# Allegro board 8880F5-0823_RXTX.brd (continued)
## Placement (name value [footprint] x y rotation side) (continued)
NOREF#889  -  []  226.83 269.63 90 top
NOREF#890  -  []  209.33 242.68 90 top
NOREF#891  -  []  412.24 144.98 90 top
NOREF#892  -  []  201.23 201.89 90 top
NOREF#893  -  []  247.25 205.56 0 top
NOREF#894  -  []  412.6 161.74 0 top
NOREF#895  -  []  405.17 131.89 0 top
NOREF#896  -  []  392.47 272.66 90 top
NOREF#897  -  []  343.98 288.86 0 top
NOREF#898  -  []  321.82 167.13 90 top
NOREF#899  -  []  175.8 201.79 90 top
NOREF#900  -  []  184.47 165.4 90 top
NOREF#901  -  []  168.13 240.88 90 top
NOREF#902  -  []  265.81 288.86 0 top
NOREF#903  -  []  66.26 271.33 90 top
NOREF#904  -  []  309.51 253.69 0 top
NOREF#905  -  []  331.94 204.65 90 top
NOREF#906  -  []  352.25 244.23 0 top
NOREF#907  -  []  310.73 187.93 0 top
NOREF#908  -  []  407.77 255.47 0 top
NOREF#909  -  []  424.47 163.09 90 top
NOREF#910  -  []  313.94 286.96 90 top
NOREF#911  -  []  192.47 230.17 90 top
NOREF#912  -  []  184.47 227.72 90 top
NOREF#913  -  []  383.73 202.38 90 top
NOREF#914  -  []  331.22 193.63 0 top
NOREF#915  -  []  352.25 241.69 0 top
NOREF#916  -  []  167.7 231.27 90 top
NOREF#917  -  []  310.41 193.37 90 top
NOREF#918  -  []  192.47 150.58 90 top
NOREF#919  -  []  119.95 187.53 0 top
NOREF#920  -  []  383.09 241.11 0 top
NOREF#921  -  []  331.38 223.52 90 top
NOREF#922  -  []  93.76 287.84 90 top
NOREF#923  -  []  259.65 265.86 90 top
NOREF#924  -  []  119.76 127 90 top
NOREF#925  -  []  284.77 146.93 90 top
NOREF#926  -  []  332.51 265.56 0 top
NOREF#927  -  []  403.41 209.61 0 top
NOREF#928  -  []  461.86 182.17 90 top
NOREF#929  -  []  167.7 186.57 90 top
NOREF#930  -  []  396.55 273.11 0 top
NOREF#931  -  []  282.9 147.38 0 top
NOREF#932  -  []  333.4 205.55 0 top
NOREF#933  -  []  254.29 264.35 90 top
NOREF#934  -  []  251.94 204.65 90 top
NOREF#935  -  []  271.34 181.37 0 top
NOREF#936  -  []  319.33 183.63 90 top
NOREF#937  -  []  300.01 288.31 90 top
NOREF#938  -  []  367.48 225.87 90 top
NOREF#939  -  []  250.74 224.72 0 top
NOREF#940  -  []  371.73 281.11 0 top
NOREF#941  -  []  405.51 209.61 0 top
NOREF#942  -  []  166.06 230.19 90 top
NOREF#943  -  []  201.23 229.07 90 top
NOREF#944  -  []  305.94 296.86 0 top
NOREF#945  -  []  209.49 168.6 90 top
NOREF#946  -  []  392.04 224.85 90 top
NOREF#947  -  []  402.14 146.88 0 top
NOREF#948  -  []  330.17 165.04 90 top
NOREF#949  -  []  272.24 244.86 90 top
NOREF#950  -  []  384.17 180.15 90 top
NOREF#951  -  []  327.25 204.35 90 top
NOREF#952  -  []  309.21 188.88 0 top
NOREF#953  -  []  388.43 163.64 0 top
NOREF#954  -  []  405.93 240.56 90 top
NOREF#955  -  []  194.09 146.68 90 top
NOREF#956  -  []  332.51 205.56 90 top
NOREF#957  -  []  239.33 183.63 90 top
NOREF#958  -  []  228.36 262.16 45 top
NOREF#959  -  []  448.94 276.41 90 top
NOREF#960  -  []  112.41 214.71 0 top
NOREF#961  -  []  310.43 187.61 90 top
NOREF#962  -  []  334.61 265.86 90 top
NOREF#963  -  []  473.6 206.05 90 top
NOREF#964  -  []  209.33 201.79 90 top
NOREF#965  -  []  293.31 272.1 0 top
NOREF#966  -  []  165.8 144.78 0 top
NOREF#967  -  []  352.55 241.37 0 top
NOREF#968  -  []  352.25 185.5 0 top
NOREF#969  -  []  343.63 225.04 90 top
NOREF#970  -  []  352.24 244.86 90 top
NOREF#971  -  []  367.48 258.38 90 top
NOREF#972  -  []  175.7 202.99 90 top
NOREF#973  -  []  254.29 204.35 90 top
NOREF#974  -  []  330.51 288.86 0 top
NOREF#975  -  []  343.31 164.72 0 top
NOREF#976  -  []  253.4 204.35 90 top
NOREF#977  -  []  225.83 204.31 0 top
NOREF#978  -  []  201.49 163.2 90 top
NOREF#979  -  []  209.49 175.56 90 top
NOREF#980  -  []  262.04 224.74 0 top
NOREF#981  -  []  272.24 181.05 90 top
NOREF#982  -  []  201.23 247.18 90 top
NOREF#983  -  []  390.34 192.28 0 top
NOREF#984  -  []  258.35 288.91 90 top
NOREF#985  -  []  106.36 190.55 0 top
NOREF#986  -  []  346.27 132.97 90 top
NOREF#987  -  []  371.48 224.6 0 top
NOREF#988  -  []  230.73 193.69 0 top
NOREF#989  -  []  107.76 238.84 0 top
NOREF#990  -  []  475.04 239.09 0 top
NOREF#991  -  []  275.82 296.86 0 top
NOREF#992  -  []  110.21 195.15 0 top
NOREF#993  -  []  463.61 214.96 0 top
NOREF#994  -  []  398.53 161.74 90 top
NOREF#995  -  []  339.33 205.56 90 top
NOREF#996  -  []  229.21 246.34 0 top
NOREF#997  -  []  188.08 289.11 90 top
NOREF#998  -  []  389.7 209.36 0 top
NOREF#999  -  []  392.47 224.4 90 top
NOREF#1000  -  []  343.95 224.74 90 top
NOREF#1001  -  []  351.34 181.37 0 top
NOREF#1002  -  []  330.73 265.55 0 top
NOREF#1003  -  []  468.01 171.53 0 top
NOREF#1004  -  []  223.56 233.86 90 top
NOREF#1005  -  []  261.63 195.43 90 top
NOREF#1006  -  []  478.57 293.82 90 top
NOREF#1007  -  []  209.08 256.4 90 top
NOREF#1008  -  []  394.05 223.21 0 top
NOREF#1009  -  []  424.98 146.33 90 top
NOREF#1010  -  []  36.1 129.71 90 top
NOREF#1011  -  []  192.47 243.88 90 top
NOREF#1012  -  []  283.21 270.2 90 top
NOREF#1013  -  []  119.7 231.22 0 top
NOREF#1014  -  []  199.59 216.47 90 top
NOREF#1015  -  []  192.47 216.45 90 top
NOREF#1016  -  []  389.7 209.36 0 top
NOREF#1017  -  []  257.09 224.74 90 top
NOREF#1018  -  []  254.29 265.56 90 top
NOREF#1019  -  []  327.15 286.96 90 top
NOREF#1020  -  []  218.16 237.06 0 top
NOREF#1021  -  []  251.62 205.56 90 top
NOREF#1022  -  []  461.96 210.36 0 top
NOREF#1023  -  []  340.61 286.96 90 top
NOREF#1024  -  []  299.59 288.86 90 top
NOREF#1025  -  []  289.29 296.86 0 top
NOREF#1026  -  []  175.7 164.3 90 top
NOREF#1027  -  []  238.3 224.74 90 top
NOREF#1028  -  []  218.16 188.49 0 top
NOREF#1029  -  []  392.73 154.88 0 top
NOREF#1030  -  []  327.57 264.65 90 top
NOREF#1031  -  []  167.7 233.47 90 top
NOREF#1032  -  []  310.43 188.88 90 top
NOREF#1033  -  []  250.5 288.86 0 top
NOREF#1034  -  []  247.57 204.65 90 top
NOREF#1035  -  []  352.55 245.18 0 top
NOREF#1036  -  []  184.47 255.15 0 top
NOREF#1037  -  []  344.37 128.27 0 top
NOREF#1038  -  []  167.7 165.4 90 top
NOREF#1039  -  []  371.48 265.11 0 top
NOREF#1040  -  []  352.24 243.59 90 top
NOREF#1041  -  []  337.09 224.74 90 top
NOREF#1042  -  []  393.74 131.34 90 top
NOREF#1043  -  []  215.96 237.06 0 top
NOREF#1044  -  []  194.09 201.29 90 top
NOREF#1045  -  []  271.04 189.18 0 top
NOREF#1046  -  []  263.14 270.2 90 top
NOREF#1047  -  []  495.08 277.31 90 top
NOREF#1048  -  []  391.8 209.36 0 top
NOREF#1049  -  []  306.83 269.63 90 top
NOREF#1050  -  []  528.1 257.36 90 top
NOREF#1051  -  []  127.55 184.33 90 top
NOREF#1052  -  []  371.73 273.11 0 top
NOREF#1053  -  []  481.96 273.87 90 top
NOREF#1054  -  []  418.12 273.37 0 top
NOREF#1055  -  []  167.7 163.2 90 top
NOREF#1056  -  []  277.17 288.86 0 top
NOREF#1057  -  []  460.93 182.17 90 top
NOREF#1058  -  []  226.85 271.67 0 top
NOREF#1059  -  []  394.66 226.38 90 top
NOREF#1060  -  []  518.38 259.9 90 top
NOREF#1061  -  []  378.33 257.11 90 top
NOREF#1062  -  []  415.61 185.72 90 top
NOREF#1063  -  []  295.96 248.49 0 top
NOREF#1064  -  []  342.08 290.13 90 top
NOREF#1065  -  []  209.59 174.36 90 top
NOREF#1066  -  []  167.7 165.4 90 top
NOREF#1067  -  []  224.65 271.67 0 top
NOREF#1068  -  []  374.88 217.11 0 top
NOREF#1069  -  []  303.84 288.86 0 top
NOREF#1070  -  []  230.41 186.34 90 top
NOREF#1071  -  []  167.7 255.15 90 top
NOREF#1072  -  []  108.27 171.02 0 top
NOREF#1073  -  []  451.68 230.2 0 top
NOREF#1074  -  []  373.73 207.21 0 top
NOREF#1075  -  []  272.25 184.86 90 top
NOREF#1076  -  []  184.47 187.92 90 top
NOREF#1077  -  []  369.63 289.12 0 top
NOREF#1078  -  []  251.94 205.86 90 top
NOREF#1079  -  []  267.84 280.1 0 top
NOREF#1080  -  []  373.93 297.12 0 top
NOREF#1081  -  []  415.6 146.88 0 top
NOREF#1082  -  []  331.94 265.86 90 top
NOREF#1083  -  []  369.38 257.11 0 top
NOREF#1084  -  []  249.6 224.74 90 top
NOREF#1085  -  []  236.27 289.16 90 top
NOREF#1086  -  []  369.38 224.6 0 top
NOREF#1087  -  []  329.85 224.74 0 top
NOREF#1088  -  []  253.4 205.56 0 top
NOREF#1089  -  []  165.8 212.85 90 top
NOREF#1090  -  []  238.3 223.52 90 top
NOREF#1091  -  []  377.48 273.16 90 top
NOREF#1092  -  []  380.59 287.22 0 top
NOREF#1093  -  []  375.22 180.15 0 top
NOREF#1094  -  []  468.85 257.36 90 top
NOREF#1095  -  []  271.31 288.86 0 top
NOREF#1096  -  []  330.74 164.72 0 top
NOREF#1097  -  []  351.34 182.64 0 top
NOREF#1098  -  []  331.06 223.82 90 top
NOREF#1099  -  []  268.01 296.86 0 top
NOREF#1100  -  []  182.57 185.42 0 top
NOREF#1101  -  []  322.62 139.64 0 top
NOREF#1102  -  []  396.22 139.89 0 top
NOREF#1103  -  []  229.51 253.69 0 top
NOREF#1104  -  []  216.96 180.71 0 top
NOREF#1105  -  []  241.82 227.13 90 top
NOREF#1106  -  []  343.95 164.74 90 top
NOREF#1107  -  []  352.25 245.5 0 top
NOREF#1108  -  []  352.25 184.23 0 top
NOREF#1109  -  []  415.61 181.32 90 top
NOREF#1110  -  []  303.56 233.86 90 top
NOREF#1111  -  []  352.25 189.82 0 top
NOREF#1112  -  []  251.33 140.14 0 top
NOREF#1113  -  []  352.24 184.86 90 top
NOREF#1114  -  []  334.29 205.55 0 top
NOREF#1115  -  []  400.85 281.11 0 top
NOREF#1116  -  []  465.81 171.53 0 top
NOREF#1117  -  []  330.74 224.72 0 top
NOREF#1118  -  []  252.83 265.86 90 top
NOREF#1119  -  []  310.73 193.69 0 top
NOREF#1120  -  []  304.61 131.64 0 top
NOREF#1121  -  []  184.47 217.55 90 top
NOREF#1122  -  []  251.62 205.56 0 top
NOREF#1123  -  []  167.7 136.27 90 top
NOREF#1124  -  []  192.57 215.25 90 top
NOREF#1125  -  []  303.26 139.64 0 top
NOREF#1126  -  []  270.04 280.1 0 top
NOREF#1127  -  []  221.56 239.06 0 top
NOREF#1128  -  []  379 288.57 90 top
NOREF#1129  -  []  383.01 139.89 0 top
NOREF#1130  -  []  184.47 174.46 90 top
NOREF#1131  -  []  200.98 258.7 90 top
NOREF#1132  -  []  397.38 180.15 90 top
NOREF#1133  -  []  249.28 225.04 90 top
NOREF#1134  -  []  216.96 192.14 0 top
NOREF#1135  -  []  184.47 256.5 90 top
NOREF#1136  -  []  388.43 180.15 0 top
NOREF#1137  -  []  424.05 163.64 90 top
NOREF#1138  -  []  229.51 189.2 0 top
NOREF#1139  -  []  342.36 163.82 90 top
NOREF#1140  -  []  199.84 162.12 90 top
NOREF#1141  -  []  263.31 164.74 0 top
NOREF#1142  -  []  209.49 148.63 90 top
NOREF#1143  -  []  342.36 165.04 90 top
NOREF#1144  -  []  352.25 242.96 0 top
NOREF#1145  -  []  453.88 214.96 0 top
NOREF#1146  -  []  262.68 223.52 90 top
NOREF#1147  -  []  107.02 171.57 0 top
NOREF#1148  -  []  112.67 171.02 0 top
NOREF#1149  -  []  312.21 144.34 0 top
NOREF#1150  -  []  219.81 213.69 90 top
NOREF#1151  -  []  250.17 163.82 90 top
NOREF#1152  -  []  379.52 188.15 0 top
NOREF#1153  -  []  398.65 289.12 0 top
NOREF#1154  -  []  377.32 163.39 0 top
NOREF#1155  -  []  318.3 223.52 90 top
NOREF#1156  -  []  390.59 195.9 90 top
NOREF#1157  -  []  398.65 297.12 0 top
NOREF#1158  -  []  378.33 241.11 90 top
NOREF#1159  -  []  120.24 171.1 0 top
NOREF#1160  -  []  250.73 264.35 90 top
NOREF#1161  -  []  404.4 241.16 90 top
NOREF#1162  -  []  199.33 240.28 0 top
NOREF#1163  -  []  286.12 288.86 90 top
NOREF#1164  -  []  209.23 189.02 90 top
NOREF#1165  -  []  257.09 163.52 90 top
NOREF#1166  -  []  118.7 188.08 0 top
NOREF#1167  -  []  378.58 273.11 90 top
NOREF#1168  -  []  250.18 182.88 0 top
NOREF#1169  -  []  246.63 142.04 0 top
NOREF#1170  -  []  192.47 148.38 90 top
NOREF#1171  -  []  251.62 205.55 0 top
NOREF#1172  -  []  310.41 253.37 90 top
NOREF#1173  -  []  167.7 192.32 90 top
NOREF#1174  -  []  272.25 182.32 90 top
NOREF#1175  -  []  165.8 240.28 90 top
NOREF#1176  -  []  400.85 249.11 0 top
NOREF#1177  -  []  223.15 211.32 90 top
NOREF#1178  -  []  254.61 205.86 90 top
NOREF#1179  -  []  263.31 224.72 0 top
NOREF#1180  -  []  166.06 135.19 90 top
NOREF#1181  -  []  385.93 178.25 0 top
NOREF#1182  -  []  385.19 281.11 0 top
NOREF#1183  -  []  201.21 290.01 90 top
NOREF#1184  -  []  201.23 214 90 top
NOREF#1185  -  []  416.03 179.42 90 top
NOREF#1186  -  []  352.55 182.64 0 top
NOREF#1187  -  []  330.17 223.82 90 top
NOREF#1188  -  []  342.04 164.72 0 top
NOREF#1189  -  []  309.05 271.67 0 top
NOREF#1190  -  []  216.96 252.14 0 top
NOREF#1191  -  []  411.99 178.25 90 top
NOREF#1192  -  []  107.76 238.84 0 top
NOREF#1193  -  []  295.96 177.06 0 top
NOREF#1194  -  []  448.94 290.38 90 top
NOREF#1195  -  []  451.68 195.91 0 top
NOREF#1196  -  []  230.43 193.37 90 top
NOREF#1197  -  []  302.71 132.91 90 top
NOREF#1198  -  []  201.23 204.09 90 top
NOREF#1199  -  []  230.43 188.88 90 top
NOREF#1200  -  []  119.95 187.53 0 top
NOREF#1201  -  []  221.56 250.49 0 top
NOREF#1202  -  []  194.09 228.47 90 top
NOREF#1203  -  []  241.6 296.61 0 top
NOREF#1204  -  []  310.83 164.63 0 top
NOREF#1205  -  []  385.32 178.25 90 top
NOREF#1206  -  []  124.35 195.15 0 top
NOREF#1207  -  []  124.1 231.22 0 top
NOREF#1208  -  []  317.66 164.74 0 top
NOREF#1209  -  []  175.7 168.6 90 top
NOREF#1210  -  []  342.04 224.74 0 top
NOREF#1211  -  []  263.85 273.37 90 top
NOREF#1212  -  []  399.07 208.81 90 top
NOREF#1213  -  []  201.49 159.65 0 top
NOREF#1214  -  []  396.55 241.11 0 top
NOREF#1215  -  []  461.86 187.32 0 top
NOREF#1216  -  []  249.28 165.04 90 top
NOREF#1217  -  []  412.37 257.37 0 top
NOREF#1218  -  []  230.43 253.37 0 top
NOREF#1219  -  []  199.59 230.19 90 top
NOREF#1220  -  []  184.47 159.65 90 top
NOREF#1221  -  []  262.04 224.72 0 top
NOREF#1222  -  []  272.25 242.96 0 top
NOREF#1223  -  []  410.52 273.37 0 top
NOREF#1224  -  []  459.28 236.14 90 top
NOREF#1225  -  []  334.61 264.65 90 top
NOREF#1226  -  []  395.2 265.37 0 top
NOREF#1227  -  []  327.57 265.86 90 top
NOREF#1228  -  []  250.49 224.74 90 top
NOREF#1229  -  []  269.94 135.19 0 top
NOREF#1230  -  []  167.7 206.29 90 top
NOREF#1231  -  []  165.8 226.57 90 top
NOREF#1232  -  []  392.66 192.88 90 top
NOREF#1233  -  []  253.72 264.65 90 top
NOREF#1234  -  []  230.73 253.69 0 top
NOREF#1235  -  []  271.04 185.5 0 top
NOREF#1236  -  []  453.84 222.5 0 top
NOREF#1237  -  []  254.29 265.56 0 top
NOREF#1238  -  []  369.63 289.12 0 top
NOREF#1239  -  []  253.33 181.33 90 top
NOREF#1240  -  []  277.5 155.38 0 top
NOREF#1241  -  []  352.25 182.32 90 top
NOREF#1242  -  []  108.01 195.15 0 top
NOREF#1243  -  []  305.83 264.31 0 top
NOREF#1244  -  []  408.63 290.39 90 top
NOREF#1245  -  []  317.66 224.74 0 top
NOREF#1246  -  []  175.7 154.88 90 top
NOREF#1247  -  []  392.24 199.18 90 top
NOREF#1248  -  []  326 288.86 90 top
NOREF#1249  -  []  230.73 243.41 0 top
NOREF#1250  -  []  311.69 288.91 90 top
NOREF#1251  -  []  118.99 166.5 90 top
NOREF#1252  -  []  352.24 181.05 90 top
NOREF#1253  -  []  406.95 131.44 90 top
NOREF#1254  -  []  177.33 187.32 90 top
NOREF#1255  -  []  374.08 195.9 90 top
NOREF#1256  -  []  465.81 222.58 0 top
NOREF#1257  -  []  116.01 222.33 0 top
NOREF#1258  -  []  301.95 290.13 90 top
NOREF#1259  -  []  320.83 254.63 0 top
NOREF#1260  -  []  331.54 252.73 90 top
NOREF#1261  -  []  272.55 245.18 0 top
NOREF#1262  -  []  309.21 253.37 0 top
NOREF#1263  -  []  333.4 265.56 0 top
NOREF#1264  -  []  333.72 264.65 90 top
NOREF#1265  -  []  399.99 181.42 90 top
NOREF#1266  -  []  271.34 241.37 0 top
NOREF#1267  -  []  367.73 290.39 90 top
NOREF#1268  -  []  83.77 247.51 90 top
NOREF#1269  -  []  118.96 174.04 90 top
NOREF#1270  -  []  256.73 132.14 0 top
NOREF#1271  -  []  546.67 300.44 90 top
NOREF#1272  -  []  396.28 163.69 90 top
NOREF#1273  -  []  168.13 186.02 90 top
NOREF#1274  -  []  333.72 205.86 90 top
NOREF#1275  -  []  288.14 286.96 0 top
NOREF#1276  -  []  105.58 234.24 90 top
NOREF#1277  -  []  184.47 206.29 90 top
NOREF#1278  -  []  310.41 186.34 90 top
NOREF#1279  -  []  221.56 190.49 0 top
NOREF#1280  -  []  394.66 258.64 90 top
NOREF#1281  -  []  201.66 199.99 90 top
NOREF#1282  -  []  333.4 204.35 90 top
NOREF#1283  -  []  216.96 240.71 0 top
NOREF#1284  -  []  230.41 253.37 90 top
NOREF#1285  -  []  175.8 160.9 90 top
NOREF#1286  -  []  184.89 213.45 90 top
NOREF#1287  -  []  473.79 191.06 90 top
NOREF#1288  -  []  410.78 131.89 0 top
NOREF#1289  -  []  201.49 151.93 90 top
NOREF#1290  -  []  121.9 238.84 0 top
NOREF#1291  -  []  66.26 273.87 90 top
NOREF#1292  -  []  184.47 242.78 90 top
NOREF#1293  -  []  451.68 239.34 0 top
NOREF#1294  -  []  35.83 128.17 90 top
NOREF#1295  -  []  201.49 146.18 0 top
NOREF#1296  -  []  317.98 165.04 90 top
NOREF#1297  -  []  127.81 175.44 90 top
NOREF#1298  -  []  230.41 183.09 90 top
NOREF#1299  -  []  397.57 131.89 0 top
NOREF#1300  -  []  185.2 290.01 90 top
NOREF#1301  -  []  390.69 224.85 0 top
NOREF#1302  -  []  201.23 217.55 90 top
NOREF#1303  -  []  259.45 288.86 90 top
NOREF#1304  -  []  192.47 191.22 90 top
NOREF#1305  -  []  309.51 189.2 0 top
NOREF#1306  -  []  108.27 171.02 0 top
NOREF#1307  -  []  122.41 178.64 0 top
NOREF#1308  -  []  240.94 211.63 90 top
NOREF#1309  -  []  182.57 171.96 0 top
NOREF#1310  -  []  386.46 139.89 0 top
NOREF#1311  -  []  408.92 265.37 0 top
NOREF#1312  -  []  309.21 187.61 0 top
NOREF#1313  -  []  184.47 201.89 90 top
NOREF#1314  -  []  418.37 241.16 90 top
NOREF#1315  -  []  230.73 246.66 0 top
NOREF#1316  -  []  262.68 164.74 90 top
NOREF#1317  -  []  351.04 249.18 0 top
NOREF#1318  -  []  459.28 168.33 0 top
NOREF#1319  -  []  250.5 288.86 0 top
NOREF#1320  -  []  408.28 129.99 0 top
NOREF#1321  -  []  177.33 201.29 90 top
NOREF#1322  -  []  328.62 290.13 90 top
NOREF#1323  -  []  273.95 155.38 0 top
NOREF#1324  -  []  296.81 275.94 0 top
NOREF#1325  -  []  271.56 288.91 90 top
NOREF#1326  -  []  385.36 194.18 90 top
NOREF#1327  -  []  385.93 161.74 0 top
NOREF#1328  -  []  199.84 175.58 90 top
NOREF#1329  -  []  310.43 247.61 90 top
NOREF#1330  -  []  463.11 230.2 0 top
NOREF#1331  -  []  309.21 183.09 0 top
NOREF#1332  -  []  279.7 155.38 0 top
NOREF#1333  -  []  127.99 214.79 0 top
NOREF#1334  -  []  309.21 243.09 0 top
NOREF#1335  -  []  411.26 179.6 90 top
NOREF#1336  -  []  272.55 189.5 0 top
NOREF#1337  -  []  339.33 265.56 90 top
NOREF#1338  -  []  245.15 288.66 90 top
NOREF#1339  -  []  336.45 164.72 0 top
NOREF#1340  -  []  120.21 178.64 0 top
NOREF#1341  -  []  106.76 217.73 90 top
NOREF#1342  -  []  395.67 133.16 90 top
NOREF#1343  -  []  192.47 246.08 90 top
NOREF#1344  -  []  346.27 130.77 90 top
NOREF#1345  -  []  272.24 242.32 90 top
NOREF#1346  -  []  450.03 210.36 0 top
NOREF#1347  -  []  94.93 190.55 0 top
NOREF#1348  -  []  215.96 188.49 0 top
NOREF#1349  -  []  322.23 173.13 90 top
NOREF#1350  -  []  331.62 205.56 0 top
NOREF#1351  -  []  333.4 205.56 90 top
NOREF#1352  -  []  409.49 163.64 0 top
NOREF#1353  -  []  310.43 193.37 0 top
NOREF#1354  -  []  495.08 257.36 90 top
NOREF#1355  -  []  209.33 228.97 90 top
NOREF#1356  -  []  247.25 205.55 0 top
NOREF#1357  -  []  222.11 240.71 0 top
NOREF#1358  -  []  210.86 187.32 90 top
NOREF#1359  -  []  201.21 276.04 90 top
NOREF#1360  -  []  328.33 247.93 0 top
NOREF#1361  -  []  106.11 234.24 0 top
NOREF#1362  -  []  424.98 146.43 90 top
NOREF#1363  -  []  495.08 274.77 90 top
NOREF#1364  -  []  450.03 210.36 0 top
NOREF#1365  -  []  392.04 241.11 90 top
NOREF#1366  -  []  110.47 178.64 0 top
NOREF#1367  -  []  412.88 139.89 0 top
NOREF#1368  -  []  240.83 254.63 0 top
NOREF#1369  -  []  165.8 199.39 90 top
NOREF#1370  -  []  351.04 185.5 0 top
NOREF#1371  -  []  331.05 264.65 90 top
NOREF#1372  -  []  229.21 187.61 0 top
NOREF#1373  -  []  381.74 249.11 0 top
NOREF#1374  -  []  272.24 183.59 90 top
NOREF#1375  -  []  192.57 242.68 90 top
NOREF#1376  -  []  253.4 205.55 0 top
NOREF#1377  -  []  385.19 249.11 0 top
NOREF#1378  -  []  415.6 146.88 0 top
NOREF#1379  -  []  391.8 217.36 0 top
NOREF#1380  -  []  98.53 238.84 0 top
NOREF#1381  -  []  217.71 276.09 0 top
NOREF#1382  -  []  396.55 241.11 0 top
NOREF#1383  -  []  167.7 244.98 90 top
NOREF#1384  -  []  66.26 290.38 90 top
NOREF#1385  -  []  331.05 204.65 90 top
NOREF#1386  -  []  340.83 174.63 90 top
NOREF#1387  -  []  398.65 249.11 0 top
NOREF#1388  -  []  209.49 164.3 90 top
NOREF#1389  -  []  338.2 246.67 0 top
NOREF#1390  -  []  343.95 223.52 90 top
NOREF#1391  -  []  472.86 174.55 90 top
NOREF#1392  -  []  239.33 176.03 0 top
NOREF#1393  -  []  342.04 224.72 0 top
NOREF#1394  -  []  259.65 204.65 90 top
NOREF#1395  -  []  108.01 222.33 0 top
NOREF#1396  -  []  263.2 232.26 90 top
NOREF#1397  -  []  468.01 214.96 0 top
NOREF#1398  -  []  319.33 236.03 90 top
NOREF#1399  -  []  167.7 176.66 90 top
NOREF#1400  -  []  98.78 195.15 0 top
NOREF#1401  -  []  408.02 287.22 0 top
NOREF#1402  -  []  371.48 257.11 0 top
NOREF#1403  -  []  339.65 205.86 90 top
NOREF#1404  -  []  456.08 186.77 0 top
NOREF#1405  -  []  310.43 194.01 0 top
NOREF#1406  -  []  424.47 163.19 90 top
NOREF#1407  -  []  339.65 204.65 90 top
NOREF#1408  -  []  274.67 286.96 0 top
NOREF#1409  -  []  404.4 225.16 90 top
NOREF#1410  -  []  210.6 255.9 90 top
NOREF#1411  -  []  184.47 219.75 90 top
NOREF#1412  -  []  326.43 288.31 90 top
NOREF#1413  -  []  306.85 271.67 0 top
NOREF#1414  -  []  242.23 173.13 90 top
NOREF#1415  -  []  409.17 297.12 0 top
NOREF#1416  -  []  352.55 185.18 0 top
NOREF#1417  -  []  239.33 236.03 90 top
NOREF#1418  -  []  459.24 219.3 0 top
NOREF#1419  -  []  201.49 178.86 90 top
NOREF#1420  -  []  230.43 183.09 0 top
NOREF#1421  -  []  104.18 191.95 90 top
NOREF#1422  -  []  383.09 289.12 0 top
NOREF#1423  -  []  278.6 147.38 0 top
NOREF#1424  -  []  383.09 289.12 0 top
NOREF#1425  -  []  483.04 239.09 0 top
NOREF#1426  -  []  396.28 180.2 90 top
NOREF#1427  -  []  184.89 145.38 90 top
NOREF#1428  -  []  230.73 186.66 0 top
NOREF#1429  -  []  240.94 151.63 90 top
NOREF#1430  -  []  351.34 245.18 0 top
NOREF#1431  -  []  201.23 241.43 0 top
NOREF#1432  -  []  251.38 223.52 90 top
NOREF#1433  -  []  106.76 215.26 0 top
NOREF#1434  -  []  410.52 241.11 0 top
NOREF#1435  -  []  218.13 214.06 0 top
NOREF#1436  -  []  118.7 182.93 90 top
NOREF#1437  -  []  201.23 190.12 90 top
NOREF#1438  -  []  396.55 241.11 0 top
NOREF#1439  -  []  396.55 257.37 0 top
NOREF#1440  -  []  175.7 250.38 90 top
NOREF#1441  -  []  201.23 206.29 90 top
NOREF#1442  -  []  413.71 178.82 0 top
NOREF#1443  -  []  312.25 271.67 90 top
NOREF#1444  -  []  155.57 289.11 90 top
NOREF#1445  -  []  168.13 159.1 90 top
NOREF#1446  -  []  412.79 209.16 90 top
NOREF#1447  -  []  107.02 174.04 90 top
NOREF#1448  -  []  329.16 296.86 0 top
NOREF#1449  -  []  306.71 144.34 0 top
NOREF#1450  -  []  118.7 195.7 0 top
NOREF#1451  -  []  396.03 146.88 0 top
NOREF#1452  -  []  316.43 132.91 90 top
NOREF#1453  -  []  328.01 286.96 0 top
NOREF#1454  -  []  192.47 250.38 90 top
NOREF#1455  -  []  329.28 225.04 90 top
NOREF#1456  -  []  301.56 182.89 0 top
NOREF#1457  -  []  117.01 234.24 90 top
NOREF#1458  -  []  463.61 179.15 0 top
NOREF#1459  -  []  118.45 231.77 0 top
NOREF#1460  -  []  260.83 234.63 90 top
NOREF#1461  -  []  369.38 241.11 0 top
NOREF#1462  -  []  199.59 158.5 0 top
NOREF#1463  -  []  175.7 222.95 90 top
NOREF#1464  -  []  406.94 131.34 90 top
NOREF#1465  -  []  251.05 265.86 90 top
NOREF#1466  -  []  309.51 247.93 0 top
NOREF#1467  -  []  393.19 222.95 90 top
NOREF#1468  -  []  303.56 245.29 90 top
NOREF#1469  -  []  413.2 164.91 90 top
NOREF#1470  -  []  262.36 296.86 0 top
NOREF#1471  -  []  495.08 259.9 90 top
NOREF#1472  -  []  230.43 247.61 90 top
NOREF#1473  -  []  115.19 128.27 0 top
NOREF#1474  -  []  252.51 205.56 0 top
NOREF#1475  -  []  250.5 288.86 0 top
NOREF#1476  -  []  261.82 290.13 90 top
NOREF#1477  -  []  272.8 157.28 0 top
NOREF#1478  -  []  511.59 276.41 90 top
NOREF#1479  -  []  248.61 290.13 90 top
NOREF#1480  -  []  222.11 192.14 0 top
NOREF#1481  -  []  220.36 248.49 0 top
NOREF#1482  -  []  343.63 163.82 90 top
NOREF#1483  -  []  400.34 194.68 90 top
NOREF#1484  -  []  192.47 259.8 90 top
NOREF#1485  -  []  256.45 224.74 0 top
NOREF#1486  -  []  302.11 129.74 0 top
NOREF#1487  -  []  353.35 288.31 90 top
NOREF#1488  -  []  398.65 273.11 0 top
NOREF#1489  -  []  252.43 132.14 0 top
NOREF#1490  -  []  254.61 204.65 90 top
NOREF#1491  -  []  297.83 174.63 90 top
NOREF#1492  -  []  229.21 193.37 0 top
NOREF#1493  -  []  218.16 177.06 0 top
NOREF#1494  -  []  326.23 173.13 0 top
NOREF#1495  -  []  221.87 295.91 0 top
NOREF#1496  -  []  263.63 225.04 90 top
NOREF#1497  -  []  482.64 235.89 90 top
NOREF#1498  -  []  235.85 288.61 90 top
NOREF#1499  -  []  425.2 161.74 90 top
NOREF#1500  -  []  412.88 131.89 0 top
NOREF#1501  -  []  317.66 164.72 0 top
NOREF#1502  -  []  450.03 234.74 0 top
NOREF#1503  -  []  182.82 203.01 90 top
NOREF#1504  -  []  405.51 217.61 0 top
NOREF#1505  -  []  339.65 265.86 90 top
NOREF#1506  -  []  249.28 163.82 90 top
NOREF#1507  -  []  387.2 207.46 0 top
NOREF#1508  -  []  412.62 289.12 0 top
NOREF#1509  -  []  397.57 131.89 0 top
NOREF#1510  -  []  279.27 296.86 0 top
NOREF#1511  -  []  400.54 171.64 0 top
NOREF#1512  -  []  301.56 242.89 0 top
NOREF#1513  -  []  377.32 188.15 0 top
NOREF#1514  -  []  377.23 224.65 90 top
NOREF#1515  -  []  298.16 248.49 0 top
NOREF#1516  -  []  388.43 163.64 0 top
NOREF#1517  -  []  351.04 244.23 0 top
NOREF#1518  -  []  287.91 280.1 0 top
NOREF#1519  -  []  259.84 145.09 0 top
NOREF#1520  -  []  346.08 288.86 0 top
NOREF#1521  -  []  384.17 163.39 90 top
NOREF#1522  -  []  318.32 131.64 0 top
NOREF#1523  -  []  300.01 288.41 90 top
NOREF#1524  -  []  352.25 249.18 90 top
NOREF#1525  -  []  252.6 288.86 0 top
NOREF#1526  -  []  118.99 171.65 0 top
NOREF#1527  -  []  306.71 139.64 0 top
NOREF#1528  -  []  305.94 288.86 0 top
NOREF#1529  -  []  166.06 162.12 90 top
NOREF#1530  -  []  312.46 131.69 90 top
NOREF#1531  -  []  238.3 288.61 0 top
NOREF#1532  -  []  184.47 176.66 90 top
NOREF#1533  -  []  252.83 205.86 90 top
NOREF#1534  -  []  239.33 236.03 0 top
NOREF#1535  -  []  184.47 151.68 90 top
NOREF#1536  -  []  397.57 131.89 0 top
NOREF#1537  -  []  247.25 265.56 0 top
NOREF#1538  -  []  383.83 209.11 0 top
NOREF#1539  -  []  260.55 136.46 90 top
NOREF#1540  -  []  108.01 195.15 0 top
NOREF#1541  -  []  405.5 257.37 90 top
NOREF#1542  -  []  298.13 214.06 90 top
NOREF#1543  -  []  230.43 193.37 0 top
NOREF#1544  -  []  384.59 179.6 90 top
NOREF#1545  -  []  385.19 241.11 0 top
NOREF#1546  -  []  308.36 262.16 45 top
NOREF#1547  -  []  296.96 252.14 0 top
NOREF#1548  -  []  319.15 288.86 0 top
NOREF#1549  -  []  397.3 209.36 0 top
NOREF#1550  -  []  113.08 129.54 0 top
NOREF#1551  -  []  119.95 222.33 0 top
NOREF#1552  -  []  450.03 234.74 0 top
NOREF#1553  -  []  511.59 259.9 90 top
NOREF#1554  -  []  375.73 193.43 90 top
NOREF#1555  -  []  241.6 296.61 0 top
NOREF#1556  -  []  408.02 239.21 0 top
NOREF#1557  -  []  410.52 241.11 0 top
NOREF#1558  -  []  451.68 214.96 0 top
NOREF#1559  -  []  239.33 243.63 90 top
NOREF#1560  -  []  192.47 218.65 90 top
NOREF#1561  -  []  247.57 265.86 90 top
NOREF#1562  -  []  184.89 254.6 90 top
NOREF#1563  -  []  383.09 273.11 0 top
NOREF#1564  -  []  184.47 260.9 90 top
NOREF#1565  -  []  385.19 265.11 0 top
NOREF#1566  -  []  254.8 296.86 0 top
NOREF#1567  -  []  478.57 291.28 90 top
NOREF#1568  -  []  218.16 248.49 0 top
NOREF#1569  -  []  329.28 163.82 90 top
NOREF#1570  -  []  343.83 171.63 90 top
NOREF#1571  -  []  218.13 274.06 0 top
NOREF#1572  -  []  375.73 199.18 90 top
NOREF#1573  -  []  331.62 205.55 0 top
NOREF#1574  -  []  251.05 205.86 90 top
NOREF#1575  -  []  177.33 255.9 90 top
NOREF#1576  -  []  397.38 163.64 90 top
NOREF#1577  -  []  396.03 180.15 0 top
NOREF#1578  -  []  406.65 239.21 90 top
NOREF#1579  -  []  168.13 254.6 90 top
NOREF#1580  -  []  518.38 273.87 90 top
NOREF#1581  -  []  257.08 132.19 90 top
NOREF#1582  -  []  273.81 286.96 90 top
NOREF#1583  -  []  118.7 222.88 0 top
NOREF#1584  -  []  237.98 225.04 90 top
NOREF#1585  -  []  292.74 288.86 0 top
NOREF#1586  -  []  209.23 195.52 90 top
NOREF#1587  -  []  473.79 239.64 0 top
NOREF#1588  -  []  247.34 133.41 90 top
NOREF#1589  -  []  309.21 247.61 0 top
NOREF#1590  -  []  124.1 238.84 0 top
NOREF#1591  -  []  334.29 265.56 90 top
NOREF#1592  -  []  340.83 234.63 90 top
NOREF#1593  -  []  230.41 248.88 90 top
NOREF#1594  -  []  230.41 188.88 90 top
NOREF#1595  -  []  249.15 296.86 0 top
NOREF#1596  -  []  272.55 249.5 0 top
NOREF#1597  -  []  175.8 215.25 90 top
NOREF#1598  -  []  200.98 256.5 90 top
NOREF#1599  -  []  395.2 281.11 0 top
NOREF#1600  -  []  404.15 273.11 0 top
NOREF#1601  -  []  388.43 146.88 0 top
NOREF#1602  -  []  310.43 183.09 90 top
NOREF#1603  -  []  376.23 209.11 0 top
NOREF#1604  -  []  273.5 148.65 90 top
NOREF#1605  -  []  177.33 242.18 90 top
NOREF#1606  -  []  415.1 163.64 0 top
NOREF#1607  -  []  380.59 255.21 0 top
NOREF#1608  -  []  352.25 183.59 90 top
NOREF#1609  -  []  271.04 182.96 0 top
NOREF#1610  -  []  332.83 205.86 90 top
NOREF#1611  -  []  388.43 146.88 0 top
NOREF#1612  -  []  168.13 227.17 90 top
NOREF#1613  -  []  167.7 241.43 90 top
NOREF#1614  -  []  313.98 143.89 90 top
NOREF#1615  -  []  182.57 144.78 0 top
NOREF#1616  -  []  453.88 230.2 0 top
NOREF#1617  -  []  127.55 219.13 90 top
NOREF#1618  -  []  209.33 187.82 90 top
NOREF#1619  -  []  310.43 248.88 90 top
NOREF#1620  -  []  342.04 164.74 0 top
NOREF#1621  -  []  263.44 135.19 0 top
NOREF#1622  -  []  201.23 242.78 90 top
NOREF#1623  -  []  231.15 159.63 90 top
NOREF#1624  -  []  298.24 288.86 0 top
NOREF#1625  -  []  272.25 189.82 0 top
NOREF#1626  -  []  418.37 289.17 90 top
NOREF#1627  -  []  459.28 211.76 90 top
NOREF#1628  -  []  381.74 265.11 0 top
NOREF#1629  -  []  313.98 131.19 90 top
NOREF#1630  -  []  165.8 199.39 0 top
NOREF#1631  -  []  315.82 129.74 0 top
NOREF#1632  -  []  352.25 182.96 0 top
NOREF#1633  -  []  369.63 289.12 0 top
NOREF#1634  -  []  387.39 297.12 0 top
NOREF#1635  -  []  332.51 265.56 90 top
NOREF#1636  -  []  415.61 179.97 90 top
NOREF#1637  -  []  192.47 189.02 90 top
NOREF#1638  -  []  199.59 145.03 90 top
NOREF#1639  -  []  192.47 154.88 90 top
NOREF#1640  -  []  259.33 204.35 90 top
NOREF#1641  -  []  460.93 225.6 90 top
NOREF#1642  -  []  253.72 265.86 90 top
NOREF#1643  -  []  528.1 259.9 90 top
NOREF#1644  -  []  199.59 189.04 90 top
NOREF#1645  -  []  172.08 291.65 90 top
NOREF#1646  -  []  385.19 232.85 0 top
NOREF#1647  -  []  396.55 273.11 0 top
NOREF#1648  -  []  367.48 242.38 90 top
NOREF#1649  -  []  226.85 211.67 0 top
NOREF#1650  -  []  234.7 286.71 90 top
NOREF#1651  -  []  201.23 231.27 90 top
NOREF#1652  -  []  217.71 216.09 0 top
NOREF#1653  -  []  201.49 159.65 90 top
NOREF#1654  -  []  407.67 129.99 90 top
NOREF#1655  -  []  415.6 146.88 0 top
NOREF#1656  -  []  331.94 205.86 90 top
NOREF#1657  -  []  192.47 205.19 90 top
NOREF#1658  -  []  300.36 188.49 0 top
NOREF#1659  -  []  413.71 178.82 90 top
NOREF#1660  -  []  310.41 188.88 90 top
NOREF#1661  -  []  272.25 185.5 0 top
NOREF#1662  -  []  392.47 256.56 90 top
NOREF#1663  -  []  211.11 146.93 90 top
NOREF#1664  -  []  184.47 145.93 0 top
NOREF#1665  -  []  304.65 271.67 0 top
NOREF#1666  -  []  261.21 286.96 0 top
NOREF#1667  -  []  385.19 224.85 0 top
NOREF#1668  -  []  229.21 248.88 0 top
NOREF#1669  -  []  379.48 239.21 90 top
NOREF#1670  -  []  166.06 189.04 90 top
NOREF#1671  -  []  256.77 165.04 90 top
NOREF#1672  -  []  385.61 208.56 90 top
NOREF#1673  -  []  249.85 164.74 0 top
NOREF#1674  -  []  228.36 202.16 45 top
NOREF#1675  -  []  110.21 222.33 0 top
NOREF#1676  -  []  184.47 204.09 90 top
NOREF#1677  -  []  167.7 200.54 90 top
NOREF#1678  -  []  463.61 222.58 0 top
NOREF#1679  -  []  237.66 164.72 0 top
NOREF#1680  -  []  384.59 179.7 90 top
NOREF#1681  -  []  310.73 246.66 0 top
NOREF#1682  -  []  381.74 281.11 0 top
NOREF#1683  -  []  313.22 288.41 90 top
NOREF#1684  -  []  352.25 242.32 90 top
NOREF#1685  -  []  258.2 186.67 0 top
NOREF#1686  -  []  184.47 241.43 90 top
NOREF#1687  -  []  451.64 222.5 0 top
NOREF#1688  -  []  462.06 291.28 90 top
NOREF#1689  -  []  369.63 273.11 0 top
NOREF#1690  -  []  192.47 162.1 90 top
NOREF#1691  -  []  463.61 214.96 0 top
NOREF#1692  -  []  172.08 272.6 90 top
NOREF#1693  -  []  304.65 211.67 0 top
NOREF#1694  -  []  351.04 245.5 0 top
NOREF#1695  -  []  192.57 174.36 90 top
NOREF#1696  -  []  165.8 131.57 0 top
NOREF#1697  -  []  295.96 188.49 0 top
NOREF#1698  -  []  182.82 243.9 90 top
NOREF#1699  -  []  246.63 130.24 90 top
NOREF#1700  -  []  348.28 296.86 0 top
NOREF#1701  -  []  304.61 131.64 0 top
NOREF#1702  -  []  336.77 165.04 90 top
NOREF#1703  -  []  327.25 205.55 0 top
NOREF#1704  -  []  319.33 176.03 90 top
NOREF#1705  -  []  226.44 294.64 90 top
NOREF#1706  -  []  410.52 289.12 0 top
NOREF#1707  -  []  221.56 171.46 0 top
NOREF#1708  -  []  411.01 209.61 0 top
NOREF#1709  -  []  252.51 205.56 90 top
NOREF#1710  -  []  271.34 182.64 0 top
NOREF#1711  -  []  485.36 257.36 90 top
NOREF#1712  -  []  199.59 145.03 0 top
NOREF#1713  -  []  331.38 224.74 90 top
NOREF#1714  -  []  396.03 163.64 0 top
NOREF#1715  -  []  333.33 241.33 90 top
NOREF#1716  -  []  253.33 241.33 90 top
NOREF#1717  -  []  230.83 224.63 0 top
NOREF#1718  -  []  385.19 257.11 0 top
NOREF#1719  -  []  297.83 234.63 90 top
NOREF#1720  -  []  175.7 175.56 90 top
NOREF#1721  -  []  333.72 204.65 90 top
NOREF#1722  -  []  272.66 288.86 90 top
NOREF#1723  -  []  247.89 204.35 90 top
NOREF#1724  -  []  232.25 211.67 90 top
NOREF#1725  -  []  387.39 281.11 0 top
NOREF#1726  -  []  223.56 173.86 90 top
NOREF#1727  -  []  339.89 288.31 90 top
NOREF#1728  -  []  331.06 225.04 90 top
NOREF#1729  -  []  450.03 191.31 0 top
NOREF#1730  -  []  449.99 217.9 0 top
NOREF#1731  -  []  261.63 173.83 90 top
NOREF#1732  -  []  369.38 241.11 0 top
NOREF#1733  -  []  167.7 201.89 90 top
NOREF#1734  -  []  413.71 148.15 90 top
NOREF#1735  -  []  106.18 160.58 90 top
NOREF#1736  -  []  408.88 133.16 90 top
NOREF#1737  -  []  297.41 213.24 0 top
NOREF#1738  -  []  482.64 192.46 90 top
NOREF#1739  -  []  106.36 190.55 0 top
NOREF#1740  -  []  463.11 186.77 0 top
NOREF#1741  -  []  371.48 232.6 0 top
NOREF#1742  -  []  177.33 146.68 90 top
NOREF#1743  -  []  290.64 288.86 0 top
NOREF#1744  -  []  373.83 192.28 90 top
NOREF#1745  -  []  555.66 300.54 90 top
NOREF#1746  -  []  272.25 181.05 90 top
NOREF#1747  -  []  327.25 265.56 90 top
NOREF#1748  -  []  419.9 288.67 90 top
NOREF#1749  -  []  260.6 286.96 90 top
NOREF#1750  -  []  192.57 228.97 90 top
NOREF#1751  -  []  286.81 272.1 0 top
NOREF#1752  -  []  501.87 273.87 90 top
NOREF#1753  -  []  342.68 163.52 90 top
NOREF#1754  -  []  249.85 164.72 0 top
NOREF#1755  -  []  199.33 185.42 0 top
NOREF#1756  -  []  312.79 288.86 90 top
NOREF#1757  -  []  250.17 165.04 90 top
NOREF#1758  -  []  343.2 172.26 90 top
NOREF#1759  -  []  471.11 230.2 0 top
NOREF#1760  -  []  375.73 193.43 0 top
NOREF#1761  -  []  250.73 265.56 90 top
NOREF#1762  -  []  115.99 130.36 90 top
NOREF#1763  -  []  284.36 272.1 90 top
NOREF#1764  -  []  459.28 211.76 0 top
NOREF#1765  -  []  339.33 204.35 90 top
NOREF#1766  -  []  327.25 265.55 0 top
NOREF#1767  -  []  390.53 146.88 0 top
NOREF#1768  -  []  399.64 144.98 0 top
NOREF#1769  -  []  251.62 204.35 90 top
NOREF#1770  -  []  414.82 281.37 0 top
NOREF#1771  -  []  167.7 132.72 90 top
NOREF#1772  -  []  302.71 145.61 90 top
NOREF#1773  -  []  366.88 239.21 0 top
NOREF#1774  -  []  415.61 183.52 90 top
NOREF#1775  -  []  415.61 179.97 0 top
NOREF#1776  -  []  222.11 252.14 0 top
NOREF#1777  -  []  167.7 217.55 90 top
NOREF#1778  -  []  330.73 265.56 0 top
NOREF#1779  -  []  229.21 188.88 0 top
NOREF#1780  -  []  334.29 264.35 90 top
NOREF#1781  -  []  201.23 244.98 90 top
NOREF#1782  -  []  201.91 145.63 90 top
NOREF#1783  -  []  237.98 165.04 90 top
NOREF#1784  -  []  264.29 280.1 0 top
NOREF#1785  -  []  351.04 182.96 0 top
NOREF#1786  -  []  423.61 188.92 90 top
NOREF#1787  -  []  339.97 264.35 90 top
NOREF#1788  -  []  379.01 288.67 90 top
NOREF#1789  -  []  271.04 249.82 0 top
NOREF#1790  -  []  201.23 219.75 90 top
NOREF#1791  -  []  381.74 297.12 0 top
NOREF#1792  -  []  319.33 176.03 0 top
NOREF#1793  -  []  471.21 175.95 0 top
NOREF#1794  -  []  237.98 223.82 90 top
NOREF#1795  -  []  326.23 233.13 0 top
NOREF#1796  -  []  352.25 184.86 90 top
NOREF#1797  -  []  167.7 173.11 90 top
NOREF#1798  -  []  107.18 246.83 90 top
NOREF#1799  -  []  192.47 168.6 90 top
NOREF#1800  -  []  393.19 239.21 90 top
NOREF#1801  -  []  392.24 194.78 90 top
NOREF#1802  -  []  231.15 219.63 90 top
NOREF#1803  -  []  390.53 171.64 0 top
NOREF#1804  -  []  324.9 288.91 90 top
NOREF#1805  -  []  310.73 193.69 0 top
NOREF#1806  -  []  248.96 164.74 0 top
NOREF#1807  -  []  398.65 281.11 0 top
NOREF#1808  -  []  463.11 186.77 0 top
NOREF#1809  -  []  271.34 189.5 0 top
NOREF#1810  -  []  341.63 255.43 90 top
NOREF#1811  -  []  456.08 195.91 0 top
NOREF#1812  -  []  414.25 154.88 0 top
NOREF#1813  -  []  272.25 249.18 90 top
NOREF#1814  -  []  456.08 171.53 0 top
NOREF#1815  -  []  201.49 174.46 90 top
NOREF#1816  -  []  182.57 212.85 90 top
NOREF#1817  -  []  275.3 155.38 0 top
NOREF#1818  -  []  199.33 226.57 90 top
NOREF#1819  -  []  456.04 222.5 0 top
NOREF#1820  -  []  385.61 208.66 90 top
NOREF#1821  -  []  459.28 183.57 0 top
NOREF#1822  -  []  401.89 180.15 0 top
NOREF#1823  -  []  175.8 133.97 90 top
NOREF#1824  -  []  252.51 265.55 0 top
NOREF#1825  -  []  423.71 181.22 90 top
NOREF#1826  -  []  279.27 288.86 0 top
NOREF#1827  -  []  221.56 242.89 0 top
NOREF#1828  -  []  473.79 196.21 0 top
NOREF#1829  -  []  342.36 223.82 90 top
NOREF#1830  -  []  322.23 233.13 90 top
NOREF#1831  -  []  406.65 287.22 90 top
NOREF#1832  -  []  415.1 163.64 0 top
NOREF#1833  -  []  168.13 172.56 90 top
NOREF#1834  -  []  201.49 149.73 90 top
NOREF#1835  -  []  352.24 249.18 90 top
NOREF#1836  -  []  310.41 187.61 90 top
NOREF#1837  -  []  301.56 171.46 0 top
NOREF#1838  -  []  351.04 184.23 0 top
NOREF#1839  -  []  115.87 167.82 90 top
NOREF#1840  -  []  332.83 204.65 90 top
NOREF#1841  -  []  192.47 182.06 90 top
NOREF#1842  -  []  165.8 226.57 0 top
NOREF#1843  -  []  472.86 166.93 90 top
NOREF#1844  -  []  75.98 290.38 90 top
NOREF#1845  -  []  184.47 247.18 90 top
NOREF#1846  -  []  415.61 185.72 90 top
NOREF#1847  -  []  451.64 222.5 0 top
NOREF#1848  -  []  419.9 240.66 90 top
NOREF#1849  -  []  122.44 171.1 0 top
NOREF#1850  -  []  229.21 186.34 0 top
NOREF#1851  -  []  263.63 223.82 90 top
NOREF#1852  -  []  332.51 264.35 90 top
NOREF#1853  -  []  410.52 273.37 0 top
NOREF#1854  -  []  310.73 253.69 0 top
NOREF#1855  -  []  397.8 163.09 90 top
NOREF#1856  -  []  330.73 204.35 90 top
NOREF#1857  -  []  475.04 239.09 0 top
NOREF#1858  -  []  317.05 288.86 0 top
NOREF#1859  -  []  352.24 182.32 90 top
NOREF#1860  -  []  388.43 163.64 0 top
NOREF#1861  -  []  242.23 233.13 90 top
NOREF#1862  -  []  100.73 238.84 0 top
NOREF#1863  -  []  253.53 140.14 0 top
NOREF#1864  -  []  373.32 181.42 90 top
NOREF#1865  -  []  112.05 246.78 90 top
NOREF#1866  -  []  209.23 209.49 90 top
NOREF#1867  -  []  119.7 231.22 0 top
NOREF#1868  -  []  249.13 140.14 0 top
NOREF#1869  -  []  261.63 255.43 90 top
NOREF#1870  -  []  467.51 186.77 0 top
NOREF#1871  -  []  397.8 163.19 90 top
NOREF#1872  -  []  373.87 171.39 0 top
NOREF#1873  -  []  344.62 131.89 90 top
NOREF#1874  -  []  351.34 185.18 0 top
NOREF#1875  -  []  501.87 276.41 90 top
NOREF#1876  -  []  459.28 192.71 0 top
NOREF#1877  -  []  450.03 182.17 0 top
NOREF#1878  -  []  127.95 222.33 0 top
NOREF#1879  -  []  201.4 254.6 90 top
NOREF#1880  -  []  199.59 171.96 0 top
NOREF#1881  -  []  184.47 149.48 90 top
NOREF#1882  -  []  259.65 204.65 90 top
NOREF#1883  -  []  332.83 265.86 90 top
NOREF#1884  -  []  177.33 133.47 90 top
NOREF#1885  -  []  271.34 245.18 0 top
NOREF#1886  -  []  400.54 188.15 0 top
NOREF#1887  -  []  84.04 287.84 90 top
NOREF#1888  -  []  252.83 264.65 90 top
NOREF#1889  -  []  118.7 195.7 0 top
NOREF#1890  -  []  392.24 196.98 90 top
NOREF#1891  -  []  417.87 257.37 0 top
NOREF#1892  -  []  274.37 147.93 90 top
NOREF#1893  -  []  379.73 271.21 90 top
NOREF#1894  -  []  184.47 244.98 90 top
NOREF#1895  -  []  254.61 265.86 90 top
NOREF#1896  -  []  390.69 257.11 0 top
NOREF#1897  -  []  329.6 164.74 90 top
NOREF#1898  -  []  380.53 217.11 0 top
NOREF#1899  -  []  167.7 145.93 90 top
NOREF#1900  -  []  271.34 189.5 0 top
NOREF#1901  -  []  411.09 146.88 90 top
NOREF#1902  -  []  352.24 183.59 90 top
NOREF#1903  -  []  118.45 231.77 0 top
NOREF#1904  -  []  375.22 180.15 0 top
NOREF#1905  -  []  175.7 232.37 90 top
NOREF#1906  -  []  218.13 214.06 90 top
NOREF#1907  -  []  230.43 246.34 90 top
NOREF#1908  -  []  389.7 209.36 0 top
NOREF#1909  -  []  417.7 154.88 0 top
NOREF#1910  -  []  230.43 186.34 90 top
NOREF#1911  -  []  165.8 158.5 90 top
NOREF#1912  -  []  317.98 225.04 90 top
NOREF#1913  -  []  417.2 171.64 0 top
NOREF#1914  -  []  376.23 209.11 0 top
NOREF#1915  -  []  201.23 247.18 90 top
NOREF#1916  -  []  295.19 271.65 90 top
NOREF#1917  -  []  182.82 189.04 90 top
NOREF#1918  -  []  408.37 258.64 90 top
NOREF#1919  -  []  111.54 290.38 90 top
NOREF#1920  -  []  284.77 288.86 0 top
NOREF#1921  -  []  235.85 296.61 0 top
NOREF#1922  -  []  412.37 265.37 0 top
NOREF#1923  -  []  219.81 273.69 90 top
NOREF#1924  -  []  165.8 254 90 top
NOREF#1925  -  []  188.08 291.65 90 top
NOREF#1926  -  []  247.25 265.56 90 top
NOREF#1927  -  []  385.18 209.11 90 top
NOREF#1928  -  []  330.73 205.56 0 top
NOREF#1929  -  []  128.05 273.87 90 top
NOREF#1930  -  []  118.74 215.34 0 top
NOREF#1931  -  []  341.63 233.83 90 top
NOREF#1932  -  []  392.73 171.64 0 top
NOREF#1933  -  []  237.57 209.63 90 top
NOREF#1934  -  []  518.38 276.41 90 top
NOREF#1935  -  []  412.62 281.37 0 top
NOREF#1936  -  []  394.05 271.21 0 top
NOREF#1937  -  []  310.43 189.52 0 top
NOREF#1938  -  []  283.25 147.43 90 top
NOREF#1939  -  []  296.96 180.71 0 top
NOREF#1940  -  []  220.36 188.49 0 top
NOREF#1941  -  []  312.25 211.67 90 top
NOREF#1942  -  []  393.19 271.21 90 top
NOREF#1943  -  []  404.4 273.16 90 top
NOREF#1944  -  []  397.38 146.88 90 top
NOREF#1945  -  []  215.96 188.49 0 top
NOREF#1946  -  []  234.33 168.13 90 top
NOREF#1947  -  []  246.67 288.16 90 top
NOREF#1948  -  []  314.71 142.44 90 top
NOREF#1949  -  []  184.89 199.99 90 top
NOREF#1950  -  []  418.38 131.89 0 top
NOREF#1951  -  []  329.85 224.72 0 top
NOREF#1952  -  []  253.4 205.56 90 top
NOREF#1953  -  []  310.43 187.61 0 top
NOREF#1954  -  []  107.02 179.19 0 top
NOREF#1955  -  []  118.33 286.94 90 top
NOREF#1956  -  []  262.36 165.04 90 top
NOREF#1957  -  []  177.33 173.86 90 top
NOREF#1958  -  []  175.7 148.38 90 top
NOREF#1959  -  []  263.83 171.63 90 top
NOREF#1960  -  []  425.7 144.98 90 top
NOREF#1961  -  []  354.27 138.37 90 top
NOREF#1962  -  []  273.95 147.38 90 top
NOREF#1963  -  []  366.88 255.21 0 top
NOREF#1964  -  []  272.25 181.69 0 top
NOREF#1965  -  []  247.57 264.65 90 top
NOREF#1966  -  []  376.15 192.88 90 top
NOREF#1967  -  []  247.89 264.35 90 top
NOREF#1968  -  []  331.05 205.86 90 top
NOREF#1969  -  []  394 217.36 0 top
NOREF#1970  -  []  304.61 131.64 0 top
NOREF#1971  -  []  251.38 164.74 90 top
NOREF#1972  -  []  330.49 224.74 90 top
NOREF#1973  -  []  309.51 243.41 0 top
NOREF#1974  -  []  409.74 146.88 0 top
NOREF#1975  -  []  273.59 272.15 90 top
NOREF#1976  -  []  256.77 223.82 90 top
NOREF#1977  -  []  402.14 146.88 0 top
NOREF#1978  -  []  419.9 288.57 90 top
NOREF#1979  -  []  175.7 236.67 90 top
NOREF#1980  -  []  303.15 211.32 90 top
NOREF#1981  -  []  252.83 204.65 90 top
NOREF#1982  -  []  332.61 288.86 0 top
NOREF#1983  -  []  271.34 249.5 0 top
NOREF#1984  -  []  378.33 224.6 90 top
NOREF#1985  -  []  401.89 180.15 0 top
NOREF#1986  -  []  381.2 258.38 90 top
NOREF#1987  -  []  381.2 242.38 90 top
NOREF#1988  -  []  461.96 174.55 0 top
NOREF#1989  -  []  351.34 189.5 0 top
NOREF#1990  -  []  394.66 274.38 90 top
NOREF#1991  -  []  468.01 179.15 0 top
NOREF#1992  -  []  230.41 187.61 90 top
NOREF#1993  -  []  229.21 183.09 0 top
NOREF#1994  -  []  182.57 199.39 90 top
NOREF#1995  -  []  420.15 131.34 90 top
NOREF#1996  -  []  420.37 255.47 90 top
NOREF#1997  -  []  199.33 199.39 0 top
NOREF#1998  -  []  167.7 247.18 90 top
NOREF#1999  -  []  309.51 183.41 0 top
NOREF#2000  -  []  309.05 211.67 0 top
NOREF#2001  -  []  339.89 288.41 90 top
NOREF#2002  -  []  250.23 132.14 0 top
NOREF#2003  -  []  318.3 224.74 90 top
NOREF#2004  -  []  201.91 172.56 90 top
NOREF#2005  -  []  166.06 148.4 90 top
NOREF#2006  -  []  239.4 296.61 0 top
NOREF#2007  -  []  295.96 177.06 0 top
NOREF#2008  -  []  252.6 296.86 0 top
NOREF#2009  -  []  272.24 182.32 90 top
NOREF#2010  -  []  397.8 179.7 90 top
NOREF#2011  -  []  394.05 239.21 0 top
NOREF#2012  -  []  332.51 204.35 90 top
NOREF#2013  -  []  483.04 195.66 0 top
NOREF#2014  -  []  230.43 254.01 0 top
NOREF#2015  -  []  390.69 241.11 0 top
NOREF#2016  -  []  333.4 264.35 90 top
NOREF#2017  -  []  554.86 298.45 0 top
NOREF#2018  -  []  251.05 204.65 90 top
NOREF#2019  -  []  192.57 147.18 90 top
NOREF#2020  -  []  405.93 288.57 90 top
NOREF#2021  -  []  22.16 130.26 90 top
NOREF#2022  -  []  373.93 281.11 0 top
NOREF#2023  -  []  96.33 238.84 0 top
NOREF#2024  -  []  410.27 257.37 0 top
NOREF#2025  -  []  230.73 193.69 0 top
NOREF#2026  -  []  404.15 289.12 0 top
NOREF#2027  -  []  259.33 205.55 0 top
NOREF#2028  -  []  406.65 271.21 90 top
NOREF#2029  -  []  404.24 146.88 0 top
NOREF#2030  -  []  450.03 225.6 0 top
NOREF#2031  -  []  167.7 258.7 90 top
NOREF#2032  -  []  463.61 171.53 0 top
NOREF#2033  -  []  352.25 243.59 90 top
NOREF#2034  -  []  320.42 131.64 0 top
NOREF#2035  -  []  271.04 242.96 0 top
NOREF#2036  -  []  351.34 242.64 0 top
NOREF#2037  -  []  334.81 296.86 0 top
NOREF#2038  -  []  398.65 241.11 0 top
NOREF#2039  -  []  402.06 217.61 0 top
NOREF#2040  -  []  107.02 166.42 90 top
NOREF#2041  -  []  381.2 290.39 90 top
NOREF#2042  -  []  84.04 290.38 90 top
NOREF#2043  -  []  417.7 146.88 0 top
NOREF#2044  -  []  346.69 128.87 90 top
NOREF#2045  -  []  383.09 241.11 0 top
NOREF#2046  -  []  299.81 213.69 90 top
NOREF#2047  -  []  477.24 195.66 0 top
NOREF#2048  -  []  127.7 231.22 0 top
NOREF#2049  -  []  379.52 171.39 0 top
NOREF#2050  -  []  398.65 225.11 0 top
NOREF#2051  -  []  395.2 297.12 0 top
NOREF#2052  -  []  118.33 271.33 90 top
NOREF#2053  -  []  460.93 210.36 90 top
NOREF#2054  -  []  465.45 276.41 90 top
NOREF#2055  -  []  471.11 186.77 0 top
NOREF#2056  -  []  459.24 219.3 90 top
NOREF#2057  -  []  108.27 178.64 0 top
NOREF#2058  -  []  201.23 215.35 90 top
NOREF#2059  -  []  115.61 191.95 90 top
NOREF#2060  -  []  182.57 254 0 top
NOREF#2061  -  []  410.52 289.12 0 top
NOREF#2062  -  []  327.7 131.09 90 top
NOREF#2063  -  []  103.93 235.64 0 top
NOREF#2064  -  []  327.57 205.86 90 top
NOREF#2065  -  []  288.74 290.13 90 top
NOREF#2066  -  []  165.8 185.42 90 top
NOREF#2067  -  []  394.66 242.38 90 top
NOREF#2068  -  []  314.55 286.96 0 top
NOREF#2069  -  []  315.16 290.13 90 top
NOREF#2070  -  []  106.76 222.88 0 top
NOREF#2071  -  []  456.08 230.2 0 top
NOREF#2072  -  []  459.24 175.86 90 top
NOREF#2073  -  []  257.09 164.74 90 top
NOREF#2074  -  []  329.6 224.74 90 top
NOREF#2075  -  []  175.7 191.22 90 top
NOREF#2076  -  []  258.1 288.86 0 top
NOREF#2077  -  []  310.43 248.88 90 top
NOREF#2078  -  []  378.75 256.56 90 top
NOREF#2079  -  []  237.66 164.74 0 top
NOREF#2080  -  []  406.65 255.47 90 top
NOREF#2081  -  []  182.82 216.47 90 top
NOREF#2082  -  []  330.51 288.86 0 top
NOREF#2083  -  []  128.05 271.33 90 top
NOREF#2084  -  []  337.9 246.35 90 top
NOREF#2085  -  []  413.1 144.98 0 top
NOREF#2086  -  []  261.42 135.74 90 top
NOREF#2087  -  []  378.75 240.66 90 top
NOREF#2088  -  []  376.23 209.11 0 top
NOREF#2089  -  []  118.74 210.19 90 top
NOREF#2090  -  []  237.98 163.82 90 top
NOREF#2091  -  []  400.24 202.38 90 top
NOREF#2092  -  []  119.95 195.15 0 top
NOREF#2093  -  []  247.25 205.56 90 top
NOREF#2094  -  []  372.72 178.25 0 top
NOREF#2095  -  []  336.77 223.82 90 top
NOREF#2096  -  []  317.83 257.63 0 top
NOREF#2097  -  []  118.7 190.55 90 top
NOREF#2098  -  []  410.78 131.89 0 top
NOREF#2099  -  []  115.61 219.13 90 top
NOREF#2100  -  []  175.7 141.67 90 top
NOREF#2101  -  []  250.18 242.88 0 top
NOREF#2102  -  []  251.06 163.82 90 top
NOREF#2103  -  []  250.74 224.74 0 top
NOREF#2104  -  []  414.57 265.37 0 top
NOREF#2105  -  []  411.99 161.74 90 top
NOREF#2106  -  []  200.98 255.15 0 top
NOREF#2107  -  []  295.96 237.06 0 top
NOREF#2108  -  []  418.37 273.42 90 top
NOREF#2109  -  []  259.97 204.35 90 top
NOREF#2110  -  []  299.81 273.69 90 top
NOREF#2111  -  []  167.7 256.5 90 top
NOREF#2112  -  []  344.37 128.27 90 top
NOREF#2113  -  []  223.56 185.29 90 top
NOREF#2114  -  []  460.93 191.31 90 top
NOREF#2115  -  []  208.98 257.6 90 top
NOREF#2116  -  []  461.96 217.98 0 top
NOREF#2117  -  []  259.88 288.31 90 top
NOREF#2118  -  []  406.19 188.15 0 top
NOREF#2119  -  []  182.57 212.85 0 top
NOREF#2120  -  []  184.47 255.15 90 top
NOREF#2121  -  []  316.97 139.64 0 top
NOREF#2122  -  []  387.39 232.85 0 top
NOREF#2123  -  []  253.72 205.86 90 top
NOREF#2124  -  []  373.87 188.15 0 top
NOREF#2125  -  []  448.94 292.92 90 top
NOREF#2126  -  []  333.4 265.56 90 top
NOREF#2127  -  []  369.38 257.11 0 top
NOREF#2128  -  []  449.99 174.46 0 top
NOREF#2129  -  []  201.49 146.18 90 top
NOREF#2130  -  []  177.33 214.75 90 top
NOREF#2131  -  []  217.41 273.24 0 top
NOREF#2132  -  []  167.7 227.72 90 top
NOREF#2133  -  []  298.13 274.06 0 top
NOREF#2134  -  []  229.51 246.66 0 top
NOREF#2135  -  []  380.59 222.95 0 top
NOREF#2136  -  []  412.62 297.12 0 top
NOREF#2137  -  []  165.8 131.57 90 top
NOREF#2138  -  []  117.26 190.55 90 top
NOREF#2139  -  []  375.73 196.98 90 top
NOREF#2140  -  []  305.83 204.31 0 top
NOREF#2141  -  []  88.64 247.45 90 top
NOREF#2142  -  []  559.43 297.18 90 top
NOREF#2143  -  []  283.91 273.37 90 top
NOREF#2144  -  []  221.56 179.06 0 top
NOREF#2145  -  []  127.7 238.84 0 top
NOREF#2146  -  []  351.34 241.37 0 top
NOREF#2147  -  []  201.23 186.57 90 top
NOREF#2148  -  []  247.25 205.55 0 top
NOREF#2149  -  []  199.59 203.01 90 top
NOREF#2150  -  []  301.56 239.06 0 top
NOREF#2151  -  []  331.06 165.04 90 top
NOREF#2152  -  []  184.47 165.4 90 top
NOREF#2153  -  []  383.73 195.88 90 top
NOREF#2154  -  []  209.23 232.37 90 top
NOREF#2155  -  []  94.68 234.24 0 top
NOREF#2156  -  []  327.57 204.65 90 top
NOREF#2157  -  []  127.3 235.64 90 top
NOREF#2158  -  []  404.4 257.42 90 top
NOREF#2159  -  []  116.01 214.71 0 top
